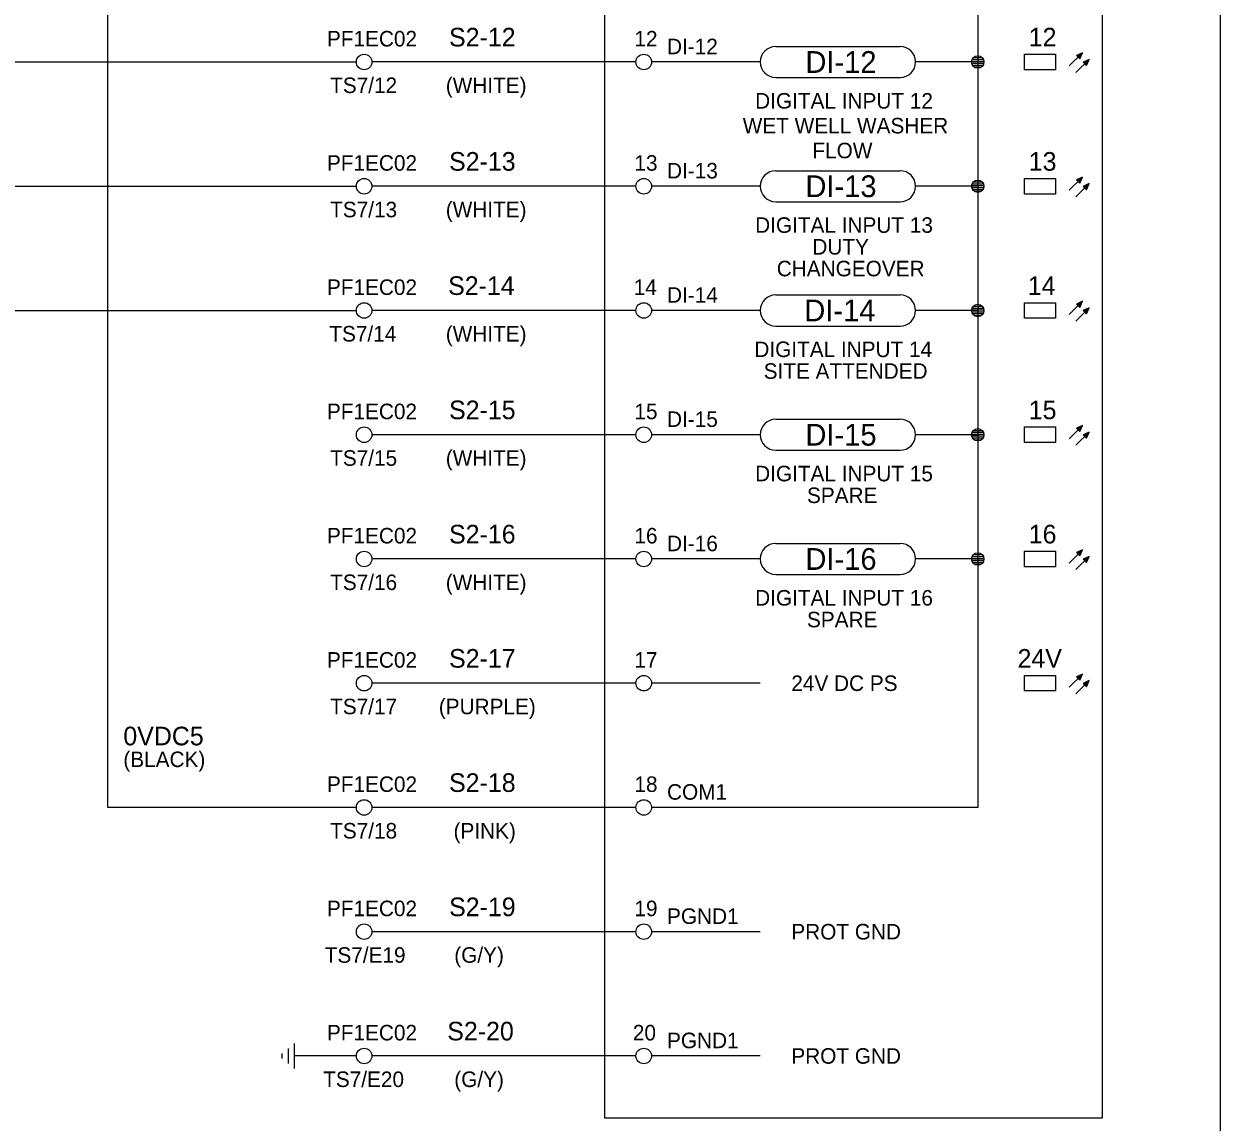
# Model space of a CAD drawing. Extents: x 0 to 841, y 0 to 594.
# Drawn here: x 636.5 to 829, y 89.4 to 266.1 of the extents above; entities that cross this region are included whole.
import ezdxf

# ---------------------------------------------------------------- set-up
doc = ezdxf.new("R2010")
doc.units = 0
for name, color, linetype in [('A1BORDER', 7, 'Continuous'), ('Default', 7, 'Continuous'), ('Level 1', 7, 'Continuous'), ('Level 10', 7, 'Continuous')]:
    doc.layers.add(name, color=color, linetype=linetype)

msp = doc.modelspace()

# ---------------------------------------------------------------- linework, layer by layer
at = {"layer": 'A1BORDER'}
msp.add_line((829, 581), (829, 15), dxfattribs=at)
at = {"layer": 'Default'}
msp.add_line((650, 140), (650, 520), dxfattribs=at)
at = {"layer": 'Level 1'}
for p, q in [((790, 480), (790, 140)), ((757.5, 262.5), (777.5, 262.5)), ((272.5, 260), (690, 260)), ((735, 260), (692.5, 260)), ((755, 260), (737.5, 260)), ((790, 260), (780, 260)), ((757.5, 257.5), (777.5, 257.5)), ((757.5, 242.5), (777.5, 242.5)), ((355, 240), (690, 240)), ((735, 240), (692.5, 240)), ((755, 240), (737.5, 240)), ((790, 240), (780, 240)), ((757.5, 237.5), (777.5, 237.5)), ((757.5, 222.5), (777.5, 222.5)), ((485, 220), (690, 220)), ((735, 220), (692.5, 220)), ((755, 220), (737.5, 220)), ((790, 220), (780, 220)), ((757.5, 217.5), (777.5, 217.5)), ((757.5, 202.5), (777.5, 202.5)), ((735, 200), (692.5, 200)), ((755, 200), (737.5, 200)), ((790, 200), (780, 200)), ((757.5, 197.5), (777.5, 197.5)), ((757.5, 182.5), (777.5, 182.5)), ((735, 180), (692.5, 180)), ((755, 180), (737.5, 180)), ((790, 180), (780, 180)), ((757.5, 177.5), (777.5, 177.5)), ((735, 160), (692.5, 160)), ((755, 160), (737.5, 160)), ((690, 140), (650, 140)), ((735, 140), (692.5, 140)), ((790, 140), (737.5, 140)), ((735, 120), (692.5, 120)), ((755, 120), (737.5, 120)), ((690, 100), (680, 100)), ((735, 100), (692.5, 100)), ((755, 100), (737.5, 100))]:
    msp.add_line(p, q, dxfattribs=at)
for points in [[(730, 540), (810, 540), (810, 90), (730, 90)], [(797.5, 261.25), (802.5, 261.25), (802.5, 258.75), (797.5, 258.75)], [(797.5, 241.25), (802.5, 241.25), (802.5, 238.75), (797.5, 238.75)], [(797.5, 221.25), (802.5, 221.25), (802.5, 218.75), (797.5, 218.75)], [(797.5, 201.25), (802.5, 201.25), (802.5, 198.75), (797.5, 198.75)], [(797.5, 181.25), (802.5, 181.25), (802.5, 178.75), (797.5, 178.75)], [(797.5, 161.25), (802.5, 161.25), (802.5, 158.75), (797.5, 158.75)]]:
    msp.add_lwpolyline(points, close=True, dxfattribs=at)
for centre, start, end in [((757.5, 260), 90, 270), ((777.5, 260), 270, 90), ((757.5, 240), 90, 270), ((777.5, 240), 270, 90), ((757.5, 220), 90, 270), ((777.5, 220), 270, 90), ((757.5, 200), 90, 270), ((777.5, 200), 270, 90), ((757.5, 180), 90, 270), ((777.5, 180), 270, 90)]:
    msp.add_arc(centre, 2.5, start, end, dxfattribs=at)
at = {"layer": 'Level 10'}
for p, q in [((789.01, 260.1), (790.99, 260.1)), ((789.08, 260.4), (790.92, 260.4)), ((789.29, 260.7), (790.71, 260.7)), ((790, 261), (790, 261)), ((804.73, 259.36), (806.86, 261.48)), ((805.79, 258.3), (807.91, 260.42)), ((805.96, 261.07), (806.67, 261.07)), ((806, 260.93), (806.61, 260.93)), ((806.14, 260.77), (806.53, 260.77)), ((806.29, 261.23), (806.74, 261.23)), ((806.3, 260.62), (806.47, 260.62)), ((806.62, 261.38), (806.81, 261.38)), ((807.02, 260.01), (807.73, 260.01)), ((807.35, 260.17), (807.8, 260.17)), ((807.68, 260.31), (807.87, 260.31)), ((789.02, 259.8), (790.98, 259.8)), ((789.13, 259.5), (790.87, 259.5)), ((789.4, 259.2), (790.6, 259.2)), ((807.06, 259.87), (807.66, 259.87)), ((807.21, 259.72), (807.6, 259.72)), ((807.36, 259.56), (807.53, 259.56)), ((789.29, 240.7), (790.71, 240.7)), ((790, 241), (790, 241)), ((804.73, 239.36), (806.86, 241.48)), ((805.96, 241.08), (806.67, 241.08)), ((806, 240.93), (806.61, 240.93)), ((806.14, 240.78), (806.53, 240.78)), ((806.29, 241.22), (806.74, 241.22)), ((806.3, 240.62), (806.47, 240.62)), ((806.62, 241.38), (806.81, 241.38)), ((789.01, 240.1), (790.99, 240.1)), ((789.02, 239.8), (790.98, 239.8)), ((789.08, 240.4), (790.92, 240.4)), ((789.13, 239.5), (790.87, 239.5)), ((789.4, 239.2), (790.6, 239.2)), ((805.79, 238.3), (807.91, 240.42)), ((807.02, 240.02), (807.73, 240.02)), ((807.06, 239.87), (807.66, 239.87)), ((807.21, 239.72), (807.6, 239.72)), ((807.35, 240.16), (807.8, 240.16)), ((807.36, 239.56), (807.53, 239.56)), ((807.68, 240.31), (807.87, 240.31)), ((804.73, 219.36), (806.86, 221.48)), ((806.62, 221.38), (806.81, 221.38)), ((789.01, 220.1), (790.99, 220.1)), ((789.02, 219.8), (790.98, 219.8)), ((789.08, 220.4), (790.92, 220.4)), ((789.13, 219.5), (790.87, 219.5)), ((789.29, 220.7), (790.71, 220.7)), ((790, 221), (790, 221)), ((805.79, 218.3), (807.91, 220.42)), ((805.96, 221.08), (806.67, 221.08)), ((806, 220.93), (806.61, 220.93)), ((806.14, 220.78), (806.53, 220.78)), ((806.29, 221.22), (806.74, 221.22)), ((806.3, 220.62), (806.47, 220.62)), ((807.02, 220.02), (807.73, 220.02)), ((807.06, 219.87), (807.66, 219.87)), ((807.21, 219.72), (807.6, 219.72)), ((807.35, 220.16), (807.8, 220.16)), ((807.36, 219.56), (807.53, 219.56)), ((807.68, 220.31), (807.87, 220.31)), ((789.4, 219.2), (790.6, 219.2)), ((789.08, 200.4), (790.92, 200.4)), ((789.29, 200.7), (790.71, 200.7)), ((790, 201), (790, 201)), ((804.73, 199.36), (806.86, 201.48)), ((805.79, 198.3), (807.91, 200.42)), ((805.96, 201.08), (806.67, 201.08)), ((806, 200.93), (806.61, 200.93)), ((806.14, 200.78), (806.53, 200.78)), ((806.29, 201.22), (806.74, 201.22)), ((806.3, 200.62), (806.47, 200.62)), ((806.62, 201.38), (806.81, 201.38)), ((807.68, 200.31), (807.87, 200.31)), ((789.01, 200.1), (790.99, 200.1)), ((789.02, 199.8), (790.98, 199.8)), ((789.13, 199.5), (790.87, 199.5)), ((789.4, 199.2), (790.6, 199.2)), ((807.02, 200.02), (807.73, 200.02)), ((807.06, 199.87), (807.66, 199.87)), ((807.21, 199.72), (807.6, 199.72)), ((807.35, 200.16), (807.8, 200.16)), ((807.36, 199.56), (807.53, 199.56)), ((790, 181), (790, 181)), ((804.73, 179.35), (806.86, 181.48)), ((805.96, 181.08), (806.67, 181.08)), ((806.29, 181.22), (806.74, 181.22)), ((806.62, 181.38), (806.81, 181.38)), ((789.01, 180.1), (790.99, 180.1)), ((789.02, 179.8), (790.98, 179.8)), ((789.08, 180.4), (790.92, 180.4)), ((789.13, 179.5), (790.87, 179.5)), ((789.29, 180.7), (790.71, 180.7)), ((789.4, 179.2), (790.6, 179.2)), ((805.79, 178.3), (807.91, 180.42)), ((806, 180.93), (806.61, 180.93)), ((806.14, 180.78), (806.53, 180.78)), ((806.3, 180.62), (806.47, 180.62)), ((807.02, 180.02), (807.73, 180.02)), ((807.06, 179.87), (807.66, 179.87)), ((807.21, 179.72), (807.6, 179.72)), ((807.35, 180.16), (807.8, 180.16)), ((807.36, 179.56), (807.53, 179.56)), ((807.68, 180.31), (807.87, 180.31)), ((804.73, 159.35), (806.86, 161.48)), ((805.79, 158.3), (807.91, 160.42)), ((805.96, 161.08), (806.67, 161.08)), ((806, 160.93), (806.61, 160.93)), ((806.14, 160.78), (806.53, 160.78)), ((806.29, 161.22), (806.74, 161.22)), ((806.3, 160.62), (806.47, 160.62)), ((806.62, 161.38), (806.81, 161.38)), ((807.02, 160.02), (807.73, 160.02)), ((807.06, 159.87), (807.66, 159.87)), ((807.35, 160.16), (807.8, 160.16)), ((807.68, 160.31), (807.87, 160.31)), ((807.21, 159.72), (807.6, 159.72)), ((807.36, 159.56), (807.53, 159.56)), ((678, 100.4), (678, 99.6)), ((679, 101.2), (679, 98.8)), ((680, 102), (680, 98))]:
    msp.add_line(p, q, dxfattribs=at)
for points in [[(806.86, 261.48), (805.88, 261.04), (806.41, 260.5)], [(807.91, 260.42), (806.94, 259.98), (807.48, 259.44)], [(806.86, 241.48), (805.88, 241.04), (806.41, 240.5)], [(807.91, 240.42), (806.94, 239.98), (807.48, 239.44)], [(806.86, 221.48), (805.88, 221.04), (806.41, 220.5)], [(807.91, 220.42), (806.94, 219.98), (807.48, 219.44)], [(806.86, 201.48), (805.88, 201.04), (806.41, 200.5)], [(807.91, 200.42), (806.94, 199.98), (807.48, 199.44)], [(806.86, 181.48), (805.88, 181.04), (806.41, 180.5)], [(807.91, 180.42), (806.94, 179.98), (807.48, 179.44)], [(806.86, 161.48), (805.88, 161.04), (806.41, 160.5)], [(807.91, 160.42), (806.94, 159.98), (807.48, 159.44)]]:
    msp.add_lwpolyline(points, close=True, dxfattribs=at)
for centre, radius in [((691.25, 260), 1.25), ((736.25, 260), 1.25), ((790, 260), 1), ((691.25, 240), 1.25), ((736.25, 240), 1.25), ((790, 240), 1), ((691.25, 220), 1.25), ((736.25, 220), 1.25), ((790, 220), 1), ((691.25, 200), 1.25), ((736.25, 200), 1.25), ((790, 200), 1), ((691.25, 180), 1.25), ((736.25, 180), 1.25), ((790, 180), 1), ((691.25, 160), 1.25), ((736.25, 160), 1.25), ((691.25, 140), 1.25), ((736.25, 140), 1.25), ((691.25, 120), 1.25), ((736.25, 120), 1.25), ((691.25, 100), 1.25), ((736.25, 100), 1.25)]:
    msp.add_circle(centre, radius, dxfattribs=at)

# ---------------------------------------------------------------- texts
at = {"layer": 'Level 1'}
for s, height, p in [('PF1EC02', 2.5, (685.27, 262.5)), ('S2-12', 3, (704.92, 262.5)), ('12', 2.5, (734.75, 262.5)), ('DI-12', 2.5, (740, 261.25)), ('12', 3, (798.21, 262.5)), ('DI-12', 3.5, (762.27, 258.25)), ('TS7/12', 2.5, (685.78, 255)), ('(WHITE)', 2.5, (704.39, 255)), ('DIGITAL INPUT 12', 2.5, (754.18, 252.5)), ('WET WELL WASHER', 2.5, (752.18, 248.5)), ('FLOW', 2.5, (763.39, 244.5)), ('PF1EC02', 2.5, (685.27, 242.5)), ('S2-13', 3, (704.92, 242.5)), ('13', 2.5, (734.75, 242.5)), ('13', 3, (798.21, 242.5)), ('DI-13', 2.5, (740, 241.25)), ('DI-13', 3.5, (762.27, 238.25)), ('TS7/13', 2.5, (685.78, 235)), ('(WHITE)', 2.5, (704.39, 235)), ('DIGITAL INPUT 13', 2.5, (754.18, 232.5)), ('DUTY', 2.5, (763.39, 229)), ('CHANGEOVER', 2.5, (757.66, 225.5)), ('S2-14', 3, (704.77, 222.5)), ('14', 3, (798.06, 222.5)), ('PF1EC02', 2.5, (685.27, 222.5)), ('14', 2.5, (734.63, 222.5)), ('DI-14', 2.5, (740, 221.25)), ('DI-14', 3.5, (762.09, 218.25)), ('TS7/14', 2.5, (685.65, 215)), ('(WHITE)', 2.5, (704.39, 215)), ('DIGITAL INPUT 14', 2.5, (754.05, 212.5)), ('SITE ATTENDED', 2.5, (755.55, 209)), ('PF1EC02', 2.5, (685.27, 202.5)), ('S2-15', 3, (704.92, 202.5)), ('15', 2.5, (734.75, 202.5)), ('15', 3, (798.21, 202.5)), ('DI-15', 2.5, (740, 201.25)), ('DI-15', 3.5, (762.27, 198.25)), ('TS7/15', 2.5, (685.78, 195)), ('(WHITE)', 2.5, (704.39, 195)), ('DIGITAL INPUT 15', 2.5, (754.18, 192.5)), ('SPARE', 2.5, (762.52, 189)), ('PF1EC02', 2.5, (685.27, 182.5)), ('S2-16', 3, (704.92, 182.5)), ('16', 2.5, (734.75, 182.5)), ('16', 3, (798.21, 182.5)), ('DI-16', 2.5, (740, 181.25)), ('DI-16', 3.5, (762.27, 178.25)), ('TS7/16', 2.5, (685.78, 175)), ('(WHITE)', 2.5, (704.39, 175)), ('DIGITAL INPUT 16', 2.5, (754.18, 172.5)), ('SPARE', 2.5, (762.52, 169)), ('PF1EC02', 2.5, (685.27, 162.5)), ('S2-17', 3, (704.92, 162.5)), ('17', 2.5, (734.75, 162.5)), ('24V', 3, (796.41, 162.5)), ('24V DC PS', 2.5, (760, 158.75)), ('TS7/17', 2.5, (685.78, 155)), ('(PURPLE)', 2.5, (703.27, 155)), ('0VDC5', 3, (652.5, 150)), ('(BLACK)', 2.5, (652.5, 146.5)), ('PF1EC02', 2.5, (685.27, 142.5)), ('S2-18', 3, (704.92, 142.5)), ('18', 2.5, (734.75, 142.5)), ('COM1', 2.5, (740, 141.25)), ('TS7/18', 2.5, (685.78, 135)), ('(PINK)', 2.5, (705.64, 135)), ('S2-19', 3, (704.93, 122.5)), ('PF1EC02', 2.5, (685.27, 122.5)), ('19', 2.5, (734.75, 122.5)), ('PGND1', 2.5, (740, 121.25)), ('PROT GND', 2.5, (760, 118.75)), ('TS7/E19', 2.5, (684.91, 115)), ('(G/Y)', 2.5, (705.76, 115)), ('PF1EC02', 2.5, (685.27, 102.5)), ('S2-20', 3, (704.63, 102.5)), ('20', 2.5, (734.5, 102.5)), ('PGND1', 2.5, (740, 101.25)), ('PROT GND', 2.5, (760, 98.75)), ('TS7/E20', 2.5, (684.66, 95)), ('(G/Y)', 2.5, (705.76, 95))]:
    msp.add_text(s, height=height, dxfattribs=at).set_placement(p)

doc.saveas('drawing.dxf')
